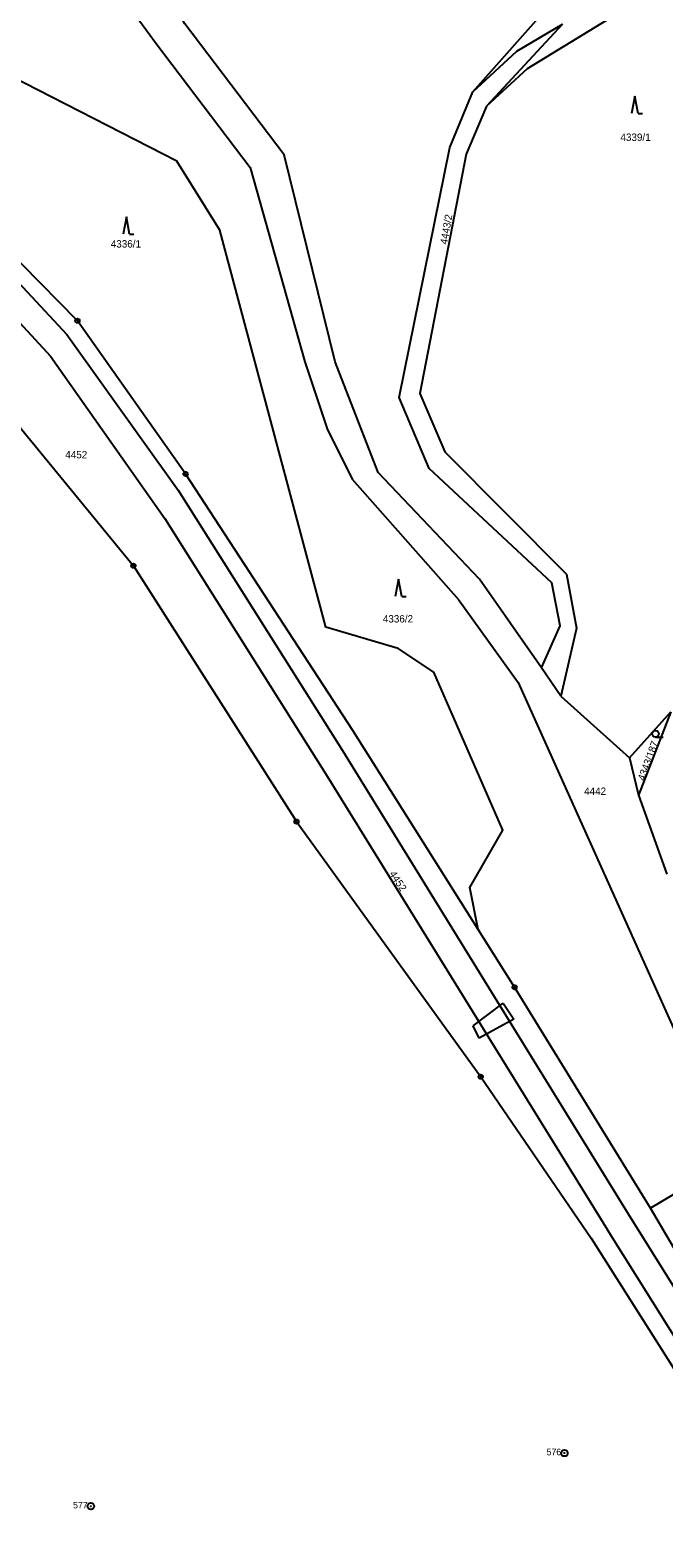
# Model space of a CAD drawing. Extents: x -733394 to -722299, y -1082822 to -1075049.
# Drawn here: x -729815.4 to -729669.4, y -1078035.5 to -1077688.1 of the extents above; entities that cross this region are included whole.
import ezdxf

# ---------------------------------------------------------------- set-up
doc = ezdxf.new("R2010")
doc.units = 0
for name, color, linetype in [('Hranice parcel', 7, 'Continuous'), ('Parcelní čísla', 7, 'Continuous'), ('Vnitřní kresba', 7, 'Continuous'), ('Značky bodu BP', 7, 'Continuous'), ('Značky kultur', 7, 'Continuous')]:
    doc.layers.add(name, color=color, linetype=linetype)

msp = doc.modelspace()

# ---------------------------------------------------------------- linework, layer by layer
at = {"layer": 'Hranice parcel'}
for p, q in [((-729692.77, -1077686.75), (-729710.26, -1077705.66)), ((-729693.15, -1077841.59), (-729697.62, -1077835.1)), ((-729693.15, -1077841.59), (-729677.33, -1077855.84)), ((-729677.33, -1077855.84), (-729667.81, -1077845.25)), ((-729667.81, -1077845.25), (-729675.27, -1077864.38)), ((-729677.33, -1077855.84), (-729675.27, -1077864.38)), ((-729675.27, -1077864.38), (-729668.75, -1077882.65)), ((-729653.62, -1077948.36), (-729672.54, -1077959.58)), ((-729632.97, -1078026.84), (-729672.54, -1077959.58))]:
    msp.add_line(p, q, dxfattribs=at)
for points in [[(-729713.46, -1077702.35), (-729664.29, -1077646.92), (-729668.15, -1077640.18), (-729729.81, -1077641.02), (-729740.95, -1077624.11), (-729744.78, -1077590.57), (-729768.83, -1077530.35), (-729802.97, -1077480.15), (-729813.39, -1077436.86), (-729807.76, -1077424.84)], [(-729699.07, -1077448.34), (-729722.15, -1077470.88), (-729727.42, -1077481.27), (-729727.66, -1077512.89), (-729714.76, -1077552.57), (-729707.85, -1077584.14), (-729700.61, -1077617.88), (-729689.02, -1077623.87), (-729678.35, -1077622.4), (-729644.67, -1077603.19), (-729629.46, -1077603.59), (-729618.58, -1077616.36), (-729620.02, -1077629.27), (-729637.52, -1077656.38), (-729651.38, -1077666.73), (-729700.92, -1077697.09), (-729710.26, -1077705.66)], [(-729697.62, -1077835.1), (-729711.9, -1077814.62), (-729735.26, -1077790.07), (-729745.16, -1077764.54), (-729756.88, -1077716.85), (-729779.79, -1077686.73), (-729789.11, -1077669.38), (-729786.14, -1077659.57), (-729772.3, -1077646.39), (-729759.5, -1077624.92), (-729758.18, -1077618.5), (-729766.21, -1077606.57)], [(-729769.13, -1077613.86), (-729768.74, -1077624.72), (-729777.4, -1077640.89), (-729791.88, -1077653.29), (-729799.37, -1077673.43), (-729786.37, -1077691.26), (-729764.74, -1077719.8), (-729752.17, -1077764.55), (-729746.97, -1077779.99), (-729741.21, -1077791.64), (-729716.77, -1077819.34), (-729702.98, -1077838.42), (-729653.62, -1077948.36)], [(-729713.46, -1077702.35), (-729703.29, -1077693.02), (-729692.77, -1077686.75)], [(-729712.22, -1077895.35), (-729714.13, -1077885.7), (-729706.52, -1077872.46), (-729722.39, -1077836.06), (-729730.66, -1077830.6), (-729747.33, -1077825.7), (-729771.73, -1077734.2), (-729781.62, -1077718.34), (-729832.91, -1077692.13)], [(-729697.62, -1077835.1), (-729693.35, -1077825.38), (-729695.21, -1077815.53), (-729723.53, -1077789.17), (-729730.44, -1077772.77), (-729718.74, -1077715.15), (-729713.46, -1077702.35)], [(-729710.26, -1077705.66), (-729715.01, -1077716.69), (-729725.66, -1077771.86), (-729719.86, -1077785.33), (-729691.83, -1077813.48), (-729689.58, -1077825.9), (-729693.15, -1077841.59)], [(-729712.22, -1077895.35), (-729741.09, -1077849.49), (-729779.63, -1077790.39), (-729804.54, -1077755.1), (-729821.58, -1077737.77), (-729843.95, -1077710.57)], [(-729857.64, -1077733.38), (-729843.37, -1077745.83), (-729825.85, -1077769.84), (-729791.65, -1077811.54), (-729754.07, -1077870.51), (-729711.61, -1077929.29), (-729686.21, -1077966.51), (-729645.9, -1078029.99), (-729620.82, -1078072.61)], [(-729672.54, -1077959.58), (-729703.82, -1077908.69), (-729712.22, -1077895.35)]]:
    msp.add_lwpolyline(points, dxfattribs=at)
at = {"layer": 'Vnitřní kresba'}
for p, q in [((-729823.69, -1077740.33), (-729807.02, -1077758.26)), ((-729829.14, -1077743.35), (-729810.76, -1077763.23)), ((-729807.02, -1077758.26), (-729781.34, -1077794.12)), ((-729810.76, -1077763.23), (-729784.4, -1077800.66)), ((-729781.34, -1077794.12), (-729743.48, -1077854.13)), ((-729784.4, -1077800.66), (-729747.02, -1077860.02)), ((-729743.48, -1077854.13), (-729677.04, -1077961.86)), ((-729747.02, -1077860.02), (-729682.38, -1077964.57)), ((-729713.36, -1077917.59), (-729706.43, -1077912.37)), ((-729706.43, -1077912.37), (-729704.03, -1077916.01)), ((-729711.96, -1077920.41), (-729713.36, -1077917.59)), ((-729704.03, -1077916.01), (-729711.96, -1077920.41)), ((-729677.04, -1077961.86), (-729630, -1078037.32)), ((-729624.23, -1078057.71), (-729682.38, -1077964.57))]:
    msp.add_line(p, q, dxfattribs=at)
at = {"layer": 'Značky bodu BP'}
for centre, radius in [((-729804.54, -1077755.1), 0.5), ((-729804.54, -1077755.1), 0.0303), ((-729779.63, -1077790.39), 0.5), ((-729779.63, -1077790.39), 0.0303), ((-729791.65, -1077811.54), 0.5), ((-729791.65, -1077811.54), 0.0303), ((-729754.07, -1077870.51), 0.5), ((-729754.07, -1077870.51), 0.0303), ((-729703.82, -1077908.69), 0.5), ((-729703.82, -1077908.69), 0.0303), ((-729711.61, -1077929.29), 0.5), ((-729711.61, -1077929.29), 0.0303), ((-729692.34, -1078016), 0.75), ((-729692.34, -1078016), 0.03), ((-729801.45, -1078028.25), 0.75), ((-729801.45, -1078028.25), 0.03)]:
    msp.add_circle(centre, radius, dxfattribs=at)
at = {"layer": 'Značky kultur'}
for p, q in [((-729676.11, -1077703.37), (-729676.86, -1077707.37)), ((-729675.36, -1077707.37), (-729676.11, -1077703.37)), ((-729675.36, -1077707.37), (-729674.36, -1077707.37)), ((-729793.28, -1077731.19), (-729794.03, -1077735.19)), ((-729792.53, -1077735.19), (-729793.28, -1077731.19)), ((-729792.53, -1077735.19), (-729791.53, -1077735.19)), ((-729730.58, -1077814.63), (-729731.33, -1077818.63)), ((-729729.83, -1077818.63), (-729730.58, -1077814.63)), ((-729729.83, -1077818.63), (-729728.83, -1077818.63)), ((-729671.34, -1077851.03), (-729669.59, -1077851.03))]:
    msp.add_line(p, q, dxfattribs=at)
msp.add_circle((-729671.34, -1077850.28), 0.75, dxfattribs=at)

# ---------------------------------------------------------------- texts
at = {"layer": 'Parcelní čísla'}
for s, p in [('4339/1', (-729679.42, -1077713.67)), ('4336/1', (-729796.86, -1077738.24)), ('4452', (-729807.35, -1077786.81)), ('4336/2', (-729734.17, -1077824.63)), ('4442', (-729687.8, -1077864.35))]:
    msp.add_text(s, height=1.7, dxfattribs=at).set_placement(p)
for s, rotation, p in [('4443/2', 80, (-729719.34, -1077737.6)), ('4343/187', 70, (-729673.9, -1077861.23)), ('4452', 303, (-729732.75, -1077882.53))]:
    msp.add_text(s, height=1.7, rotation=rotation, dxfattribs=at).set_placement(p)
at = {"layer": 'Značky bodu BP'}
for s, p in [('576', (-729696.44, -1078016.5)), ('577', (-729805.55, -1078028.75))]:
    msp.add_text(s, height=1.5, dxfattribs=at).set_placement(p)

doc.saveas('drawing.dxf')
